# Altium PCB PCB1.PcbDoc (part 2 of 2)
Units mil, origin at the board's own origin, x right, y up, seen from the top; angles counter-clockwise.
Board outline 6184.85 x 2780 mil, 2 copper layers (Top Layer, Bottom Layer); 130 components, 145 nets, 531 pads, 99 vias.
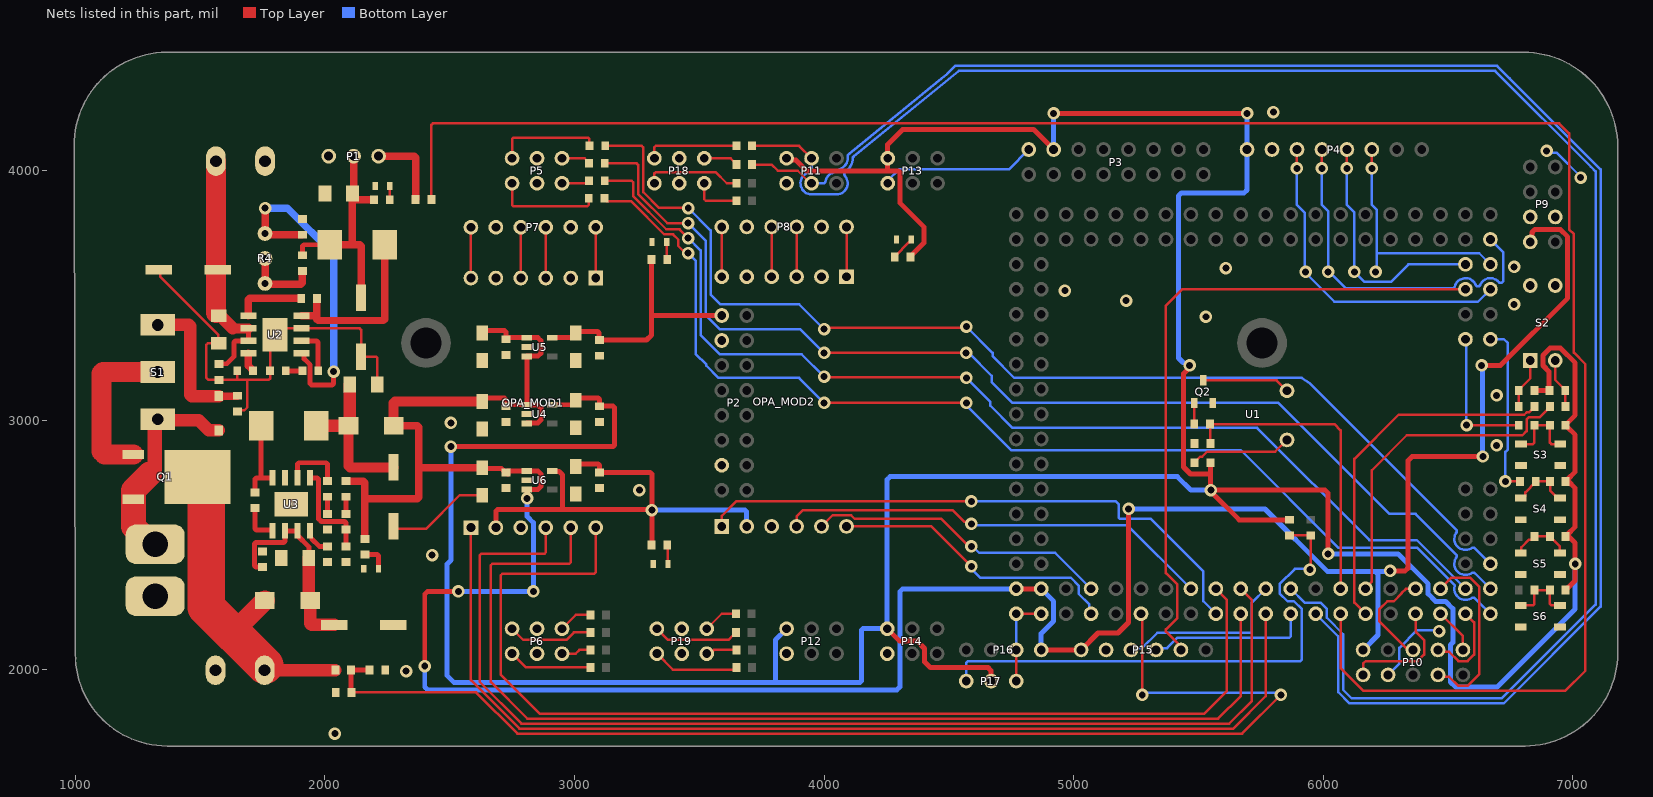
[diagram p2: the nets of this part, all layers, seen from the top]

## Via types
v1: diameter 50, hole 28, Top Layer to Bottom Layer, 99 vias

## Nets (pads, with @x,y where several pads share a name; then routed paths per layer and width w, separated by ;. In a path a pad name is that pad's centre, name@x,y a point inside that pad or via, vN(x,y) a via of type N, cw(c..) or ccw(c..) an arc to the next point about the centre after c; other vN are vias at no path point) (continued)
20.6: R42.2 U1.49 | length 555
  Top Layer w10: v1(6575,2980.91) 6782.6,2980.91 R42.2@6783.5,2980
  Bottom Layer w10: U1.49@6570,3325 6572.5,3322.5 6572.5,2983.41 v1(6575,2980.91)
20.7: R43.2 U1.50 | length 693.4
  Top Layer w10: v1(6730,2755) R43.2@6788.5,2755
  Bottom Layer w10: U1.50@6670,3325 6724.14,3325 6740,3309.14 6740,2883.43 6730,2873.43 v1(6730,2755)
20.10: P15.5 U1.53 | length 2668.7
  Top Layer w10: P15.5@5430,2080 5430,2093.27 5370,2153.27 5370,2162.03 5414.53,2206.56 5414.53,2343.44 5370,2387.97 5370,3460 5435,3525 U1.53@6570,3525
20.11: P4.3 U1.54 | length 1317.8
  Top Layer w10: v1(5895,4010) P4.3@5895,4085
  Bottom Layer w10: v1(5895,4010) 5895,3862.97 5925.47,3832.5 5925.47,3599.53 v1(5930,3595) 5930,3590 6045,3475 6620,3475 U1.54@6670,3525
20.12: P4.5 U1.55 | length 993
  Top Layer w10: v1(6095,4010) P4.5@6095,4085
  Bottom Layer w10: v1(6095,4010) 6095,3862.97 6125,3832.97 v1(6125,3595) 6165,3555 6271.17,3555 6341.17,3625 U1.55@6570,3625
20.13: P4.6 U1.56 | length 973.8
  Top Layer w10: v1(6195,4010) P4.6@6195,4085
  Bottom Layer w10: v1(6195,4010) 6195,3862.97 6215,3842.97 6215,3669.53 ; v1(6210,3595) 6215,3600 6215,3669.53 ; U1.56@6670,3625 6625.47,3669.53 6215,3669.53
20.14: P4.4 U1.57 | length 1470.9
  Top Layer w10: v1(5995,4010) P4.4@5995,4085
  Bottom Layer w10: v1(5995,4010) 5995,3862.97 6020,3837.97 v1(6020,3595) 6025,3595 6090,3530 6521.72,3530 6524.65,3532.93 6526.58,3534.86 cw(c6570,3525) 6610.83,3542.76 ccw(c6620,3546.75) 6629.15,3542.73 cw(c6670,3525) 6703.67,3554.14 6703.91,3553.9 6706.84,3550.97 6710.98,3550.97 6715.13,3550.97 6718.05,3553.9 6720.98,3556.82 6720.98,3674.02 U1.57@6670,3725
21.2: R19.1 U1.38 | length 4365.8
  Top Layer w10: R19.1@3121.5,3960 3229.14,3960 3235,3954.14 3235,3898.43 3367.68,3765.75 3394.85,3765.75 3395.6,3765 3421.06,3765 v1(3455.7,3730.35) ; v1(4000,3175) 4002.5,3172.5 4567.5,3172.5 v1(4570,3170)
  Bottom Layer w10: v1(3455.7,3730.35) 3505.47,3680.58 3505.47,3341.56 3582.5,3264.53 3910.47,3264.53 v1(4000,3175) ; v1(4570,3170) 4666.56,3073.44 4666.56,3058.44 4755.47,2969.53 5735.47,2969.53 6185,2520 6375,2520 U1.38@6570,2325
21.3: R20.2 U1.39 | length 4505.9
  Top Layer w10: R20.2@3120,3890 3120,3888.03 3130.75,3877.28 3227.86,3877.28 3359.4,3745.75 3386.57,3745.75 3387.32,3745 3395,3745 3415.7,3724.3 3415.7,3699.3 3445,3670 v1(3455,3670) ; v1(4000,3070) v1(4570,3070)
  Bottom Layer w10: v1(3455,3670) 3485,3640 3485,3266.17 3528.28,3222.89 3528.28,3218.75 3577.03,3170 3900,3170 v1(4000,3070) ; v1(4570,3070) 4570,3060 4749.53,2880.47 5669.53,2880.47 6060,2490 6376.72,2490 6526.59,2340.13 6526.59,2335.98 6526.59,2334.91 ccw(c6570,2325) 6597.56,2290.03 6600.83,2290.03 6604.97,2290.03 6624.56,2270.44 U1.39@6670,2225
21.4: R21.1 U1.40 | length 4558
  Top Layer w10: R21.1@3121.5,4030 3122.28,4029.22 3249.14,4029.22 3255,4023.36 3255,3906.72 3371.72,3790 3454.65,3790 v1(3455,3790.35) ; v1(4000,3270) v1(4569.18,3270)
  Bottom Layer w10: v1(3455,3790.35) 3525.47,3719.87 3525.47,3421.56 3582.5,3364.53 3905.47,3364.53 v1(4000,3270) ; v1(4569.18,3270) 4580,3270 4671.56,3178.44 4671.56,3153.44 4755.47,3069.53 5820.47,3069.53 6265,2625 6370,2625 6532.1,2462.9 6535.03,2459.97 6535.03,2455.83 6535.03,2452.56 ccw(c6570,2425) 6597.56,2390.03 6600.83,2390.03 6604.97,2390.03 6607.9,2387.1 U1.40@6670,2325
21.5: R22.2 U1.41 | length 4554.5
  Top Layer w10: R22.2@3122.99,4100 3268.83,4100 3275.47,4093.36 3275.47,3914.53 3339.22,3850.78 3455.38,3850.78 v1(3455.82,3850.34) ; v1(4000,3365) 4005,3370 4565,3370 v1(4570,3375)
  Bottom Layer w10: v1(3455.82,3850.34) 3545.47,3760.69 3545.47,3504.53 3585.47,3464.53 3900.47,3464.53 v1(4000,3365) ; v1(4570,3375) 4675.05,3269.95 4675.05,3256.98 4762.03,3170 5911.53,3170 5914.58,3170 5946.36,3148.64 5947.05,3147.95 6532.1,2562.9 6535.03,2559.97 6535.03,2555.83 6535.03,2552.56 ccw(c6570,2525) 6597.56,2490.03 6600.83,2490.03 6604.97,2490.03 6607.9,2487.1 U1.41@6670,2425
22.0: P10.5 U1.34 | length 409.7
  Top Layer w10: P10.5@6360,2080 6350.61,2089.39 6330.61,2089.39 6225.47,2194.53 6225.47,2243.44 6257.03,2275 6282.97,2275 6314.53,2306.56 6314.53,2307.5 6331.33,2324.3 6369.3,2324.3 U1.34@6370,2325
22.1: P10.1 U1.35 | length 182.3
  Top Layer w10: U1.35@6470,2225 6560,2135 P10.1@6560,2080
22.2: P10.4 U1.36 | length 741.9
  Top Layer w10: P10.4@6460,1980 6467.5,1972.5 6504.53,1972.5 6541.56,1935.47 6578.44,1935.47 6624.53,1981.56 6624.53,2333.44 6588.44,2369.53 6514.53,2369.53 U1.36@6470,2325
22.3: P10.3 U1.37 | length 351.5
  Top Layer w10: P10.3@6460,2080 6467.5,2072.5 6504.53,2072.5 6541.56,2035.47 6578.44,2035.47 6604.53,2061.56 6604.53,2190.47 U1.37@6570,2225
23.1: P10.10 U1.33 | length 482.4
  Top Layer w10: P10.10@6160,1980 6160,2025 6170.47,2035.47 6378.44,2035.47 6404.53,2061.56 6404.53,2119.38 6370,2153.9 U1.33@6370,2225
33.4: P15.3 U1.22 | length 709.3
  Bottom Layer w10: P15.3@5230,2080 5237.5,2087.5 5274.53,2087.5 5335,2147.97 5708.67,2147.97 5714.53,2153.83 5714.53,2269.53 U1.22@5770,2325
33.5: P15.4 U1.23 | length 653.5
  Bottom Layer w10: P15.4@5330,2080 5337.5,2087.5 5374.53,2087.5 5415,2127.97 5864.14,2127.97 5870,2133.83 U1.23@5870,2225
33.6: P11.3 R46.1 U1.24 | length 7452.1
  Top Layer w10: R46.1@3711.5,4100 3900,4100 P11.3@3950,4050
  Bottom Layer w10: P11.3@3950,4050 3950,4000.39 3948.14,3997.79 cw(c3940,4003.6) 3941.89,3993.78 ccw(c3950,3950) 3911.59,3972.53 ccw(c3950,3950) 3950,3905.47 4034.39,3905.47 ccw(c4034.39,3915.47) 4035.34,3905.52 4040.84,3906.05 cw(c4041.8,3896.09) 4043.24,3905.99 ccw(c4050,3950) 4083.96,3978.8 cw(c4091.53,3985.34) 4081.53,3985.36 ccw(c3977.43,3986.62) 4081.52,3988 cw(c4091.52,3988.11) 4085.92,3996.4 ccw(c4050,4050) 4114.51,4051.55 4114.51,4052.47 4117.79,4055.76 4117.84,4055.8 4118.5,4056.34 4539.38,4400 6688.65,4400 7072.61,4016.04 7091.62,3997.03 7091.62,2261.77 6715.33,1885.47 6114.53,1885.47 6080.47,1919.53 6080.47,2142.81 6014.53,2208.76 6014.53,2243.44 5988.44,2269.53 5925.47,2269.53 U1.24@5870,2325
33.7: P11.4 R47.2 U1.25 | length 7129.6
  Top Layer w10: R47.2@3711.5,4025 3790,4025 3815,4000 3894.6,4000 3944.6,3950 P11.4@3950,3950
  Bottom Layer w10: P11.4@3950,3950 4000.54,3950 4003.47,3952.93 4005.78,3955.24 cw(c4050,3950) 4030.87,3990.21 ccw(c4026.52,3999.21) 4031.86,3990.76 cw(c4057.95,3949.96) 4044.65,3996.53 4045.56,3997.02 4071.14,4010.81 ccw(c4050,4050) 4094.51,4051.29 4094.51,4051.55 4094.51,4060.76 4104.37,4070.62 4104.48,4070.71 4110.66,4076.11 4471.02,4370 4493.7,4388.52 4494.44,4389.19 4525.25,4420 6696.94,4420 6746.95,4369.98 7111.62,4005.32 7111.62,2253.48 6723.61,1865.47 6106.24,1865.47 6060.47,1911.24 6060.47,2134.53 U1.25@5970,2225
33.9: R8.1 U1.27 | length 8326.6
  Top Layer w10: R8.1@2426.5,3885 2426.5,4184.14 2432.35,4190 6944.93,4190 6985,4149.93 6985,3765.4 7004.53,3745.87 7004.53,3270.96 7050,3225.49 7050,1996.33 6969.14,1915.47 6161.56,1915.47 6070,2007.03 U1.27@6070,2225
33.10: R30.1 R31.1 U1.28 | length 1247.6
  Top Layer w10: R31.1@5547.84,2906.81 5546.5,2908.15 R30.1@5546.5,2985 6045,2985 6070,2960 U1.28@6070,2325
33.11: R40.2 U1.29 | length 1447.9
  Top Layer w10: U1.29@6170,2225 6125.47,2269.53 6125.47,2845.47 6302.28,3022.28 6805.82,3022.28 6816.25,3032.72 6826.18,3032.72 6846.5,3053.03 R40.2@6846.5,3055
33.12: R41.2 U1.30 | length 1332.8
  Top Layer w10: U1.30@6170,2325 6170,2329.69 6195,2354.69 6195,2800 6335,2940 6798.18,2940 6815,2956.82 6815,3003.18 6824.53,3012.72 6868.19,3012.72 6908.5,3053.03 R41.2@6908.5,3055
A0: OPA_MOD1.7 U1.21 | length 4260.1
  Top Layer w10: OPA_MOD1.7@2585,2570 2585,1959.14 2779.14,1765 5640,1765 5770,1895 U1.21@5770,2225
A1: OPA_MOD1.10 U1.20 | length 4544.8
  Top Layer w10: OPA_MOD1.10@2885,2570 2885,2470.86 2879.14,2465 2625.86,2465 2620,2459.14 2620,1952.43 2787.43,1785 5623.67,1785 5714.53,1875.86 5714.53,2280.47 U1.20@5670,2325
A2: OPA_MOD1.11 U1.19 | length 4364.5
  Top Layer w10: OPA_MOD1.11@2985,2570 2985,2430.86 2979.14,2425 2670.86,2425 2665,2419.14 2665,1950.86 2810.86,1805 5579.14,1805 5670,1895.86 U1.19@5670,2225
A3: OPA_MOD1.12 U1.18 | length 4401.4
  Top Layer w10: OPA_MOD1.12@3085,2570 3085,2390.86 3079.14,2385 2711.33,2385 2705.47,2379.14 2705.47,1979.53 2860,1825 5523.67,1825 5614.53,1915.86 5614.53,2280.47 U1.18@5570,2325
A4: OPA_MOD2.7 U1.17 | length 2334.1
  Top Layer w10: OPA_MOD2.7@3590,2575 3590,2617.22 3647.78,2675 v1(4590,2675)
  Bottom Layer w10: v1(4590,2675) 5169.14,2675 5180,2664.14 5180,2610.86 5185.91,2604.95 5310.05,2604.95 5520,2395 5520,2275 U1.17@5570,2225
A5: OPA_MOD2.10 U1.16 | length 1760.8
  Top Layer w10: OPA_MOD2.10@3890,2575 3890,2615 3915,2640 4515,2640 4562.35,2592.65 4582.35,2592.65 v1(4590,2585)
  Bottom Layer w10: v1(4590,2585) 4594.53,2580.47 5214.53,2580.47 U1.16@5470,2325
A11: C27.1 R27.2 R28.1 U1.11 | length 4906.3
  Top Layer w10: R28.1@2106.5,1910 2605.86,1910 2770.86,1745 5675,1745 v1(5830,1900) ; U1.11@5270,2225 5274.53,2220.47 5274.53,1900.47 v1(5275,1900)
  Top Layer w20: R28.1@2105,1911.5 R27.2@2105,2000 C27.1@2178.5,2000
  Bottom Layer w10: v1(5275,1900) 5282.5,1907.5 5822.5,1907.5 v1(5830,1900)
A16: OPA_MOD2.11 U1.8 | length 1220.4
  Top Layer w10: OPA_MOD2.11@3990,2575 4034.53,2619.53 4108.44,2619.53 4122.97,2605 4470,2605 4580,2495 v1(4590,2495)
  Bottom Layer w10: v1(4590,2495) 4595.62,2495 4621.1,2469.53 4925.47,2469.53 U1.8@5070,2325
A17: OPA_MOD2.12 U1.7 | length 1167.7
  Top Layer w10: OPA_MOD2.12@4090,2575 4430,2575 v1(4590,2415)
  Bottom Layer w10: v1(4590,2415) 4590,2405 4625,2370 4985,2370 4985.47,2369.53 4988.44,2369.53 5020,2337.97 5020,2305 5063.51,2261.49 5063.51,2231.49 U1.7@5070,2225
GND: C1.2 C2.1 C3.1 C5.2 C6.2 C7.1 C8.2 C9.1 C10.2 C12.1 C13.2 C14.1 C15.2 C16.1 C17.2 C18.1 C19.2 C20.1 C21.2 C22.1 C23.2 C24.1 C25.2 C26.1 C27.2 DCIN.2 DCOUT1.2 DCOUT2.2 LED3V3.C LED5V.C LEDCAM.C LEDOP.C LEDSteer.C OPA_MOD1.2 OPA_MOD1.5 OPA_MOD1.9 OPA_MOD2.2 OPA_MOD2.5 OPA_MOD2.9 P1.3 P2.4 P2.14 P3.2 P4.2 P5.3 P5.4 P6.3 P6.4 P7.2 P7.5 P8.2 P8.5 P9.5 P9.6 P10.8 P11.6 P12.6 P13.6 P14.6 P15.2 P16.2 P17.1 P18.3 P18.4 P19.3 P19.4 Q2.2 R1.1 R2.1 R5.2 R9.1 R12.1 R28.2 R31.2 S2.3 S2.4 S3.1 S4.1 S5.1 S6.1 U1.1 U1.3 U2.0 U2.7 U3.0 U3.7 U4.2 U5.2 U6.2 | length 3769.1
  Top Layer w10: C1.2@1333.78,3603.5 1340.76,3596.52 1340.76,3574.68 1572.2,3343.24 1572.2,3311.3 C2.1@1575,3308.5 1530.86,3308.5 1525,3302.65 1525,3170 1532.99,3162.01 C3.1@1575,3162.01 ; C3.1@1575.36,3161.65 1648.5,3161.65 ; R2.1@1648.5,3198.5 1648.5,3161.65 ; R1.1@1650,3035.51 1654.57,3040.08 1676.86,3040.08 1689.14,3052.36 1689.14,3161.65 ; C12.1@2210.12,3143.5 2210.12,3249.54 2204.26,3255.39 C6.2@2145,3255.39 2145,3362.65 2139.14,3368.5 1825,3368.5 U2.0@1800,3343.5 1780,3323.5 1780,3167.5 1774.14,3161.65 1689.14,3161.65 ; C13.2@2275,2575.39 2285.39,2565 2405,2565 2539.88,2699.88 C23.2@2630,2699.88 ; P17.1@4770,1955 P16.2@4770,2080 ; U1.1@4770,2225 U1.3@4870,2225 ; 1648.5,3161.65 1689.14,3161.65
  Bottom Layer w10: P13.6@4255,3950 4255,3960 4300.47,4005.47 4740.47,4005.47 P3.2@4820,4085 ; P16.2@4770,2080 U1.1@4770,2225 ; P10.8@6260,1980 6305.47,2025.47 6305.47,2088.44 6376.28,2159.25 6460.75,2159.25 v1(6465,2155) ; v1(6895,4080) 6902.03,4072.97 6935,4072.97 7030,3977.97 7030,3973.8 v1(7031.62,3972.18)
  other v1: 2040,1745 2325,1995 2430,2460 3260,2720 6695,2900 2505,2990 6695,3100 5530,3415 6765,3465 5210,3480 4965,3520 5610,3610 6765,3615 5800,4235
NetB1_1: B1.1 R29.2 | length 409.1
  Top Layer w10: R29.2@5485,2830 5485,2831.97 5507.12,2854.09 5515.09,2854.09 5535.09,2874.09 5807.52,2874.09 B1.1@5855,2921.57
NetB1_2: B1.2 Q2.3 | length 352.3
  Top Layer w10: Q2.3@5520,3160.28 5813.15,3160.28 B1.2@5855,3118.43
NetC4_1: C4.1 U2.1 | length 277.9
  Top Layer w30: U2.1@1693.7,3418.5 1693.7,3482.65 1699.56,3488.5 C4.1@1905,3488.5
NetC4_2: C4.2 L2.1 U2.8 | length 719.7
  Top Layer w10: 1966.5,3418.5 1967.99,3420
  Top Layer w30: U2.8@1906.3,3418.5 1966.5,3418.5 ; C4.2@1967.99,3488.5 1967.99,3420 1967.99,3405.86 1973.85,3400 2234.38,3400 2240.24,3405.86 L2.1@2240.24,3703.5
NetC7_2: C7.2 R7.1 | length 67
  Top Layer w20: C7.2@1842.99,3198.5 R7.1@1910,3198.5
NetC8_1: C8.1 C9.2 C10.1 D2.K U3.2 U3.3 | length 831.4
  Top Layer w10: U3.3@1890,2538.5 U3.3@1890,2557.2
  Top Layer w20: C10.1@1750,2412.01 1723.14,2412.01 1717.28,2417.87 1717.28,2504.85 1723.14,2510.71 1834.14,2510.71 1840,2516.57 U3.2@1840,2557.2 U3.3@1890,2557.2 ; U3.3@1890,2538.5 1935.24,2493.27 C9.2@1935.24,2448.5
  Top Layer w50: C9.2@1935.24,2448.5 1935.24,2283.82 D2.K@1940.55,2278.5 1940.55,2185.86 1946.41,2180 C8.1@2036.89,2180
NetC11_1: C11.1 U3.1 | length 156.2
  Top Layer w10: U3.1@1787.2,2560 U3.1@1790,2557.2
  Top Layer w20: C11.1@1720,2648.5 1720,2565.86 1725.86,2560 U3.1@1787.2,2560
NetC11_2: C11.2 L1.1 U3.8 | length 333.6
  Top Layer w20: C11.2@1720,2711.5 1720,2763.95 1725.86,2769.8 1744.76,2769.8 ; L1.1@1744.76,2978.5 1744.76,2769.8 ; U3.8@1790,2769.8 1744.76,2769.8
NetC12_2: C12.2 C13.1 D3.A L1.2 | length 640.5
  Top Layer w10: D3.A@2094.45,2978.5 D3.A@2099.88,2983.94
  Top Layer w40: D3.A@2094.45,2978.5 2094.45,2817.47 2100.31,2811.61 C13.1@2275,2811.61
  Top Layer w50: L1.2@1965.24,2978.5 D3.A@2094.45,2978.5 ; D3.A@2099.88,2983.94 C12.2@2099.88,3143.5
NetC14_2: C14.2 R14.1 | length 68.5
  Top Layer w20: C14.2@2010,2625 R14.1@2010,2693.5
NetD1_A: D1.A R1.2 S1.3 | length 598.7
  Top Layer w10: R1.2@1648.9,3097.4 R1.2@1650,3098.5
  Top Layer w30: D1.A@1575,3097.4 R1.2@1648.9,3097.4
  Top Layer w50: S1.3@1330,3382.48 1454.14,3382.48 1460,3376.62 1460,3103.26 1465.86,3097.4 D1.A@1575,3097.4
NetD1_K: D1.K DCIN.1 Q1.3 S1.1 | length 851.4
  Top Layer w10: DCIN.1@1303.25,2503.5 DCIN.1@1320,2503.5 ; S1.1@1330,3004.53 S1.1@1334.53,3000
  Top Layer w50: S1.1@1334.53,3000 1495,3000 1535.39,2959.61 D1.K@1575,2959.61
  Top Layer w60: 1298.11,2784.57 1318.11,2804.57 1318.11,2992.64 S1.1@1330,3004.53
  Top Layer w100: 1298.11,2784.57 1232.13,2718.58 1232.13,2574.63 DCIN.1@1303.25,2503.5
NetLED3V3_A: LED3V3.A R16.2 | length 99.1
  Top Layer w10: R16.2@4283.5,3655 4283.5,3656.97 4340.79,3714.25 4343.7,3714.25 4349.53,3720.08 LED3V3.A@4349.53,3725
NetLED5V_A: LED5V.A R13.1 | length 108.1
  Top Layer w20: R13.1@2160,2462.01 2208.67,2462.01 2214.53,2456.15 LED5V.A@2214.53,2405
NetLEDCAM_A: LEDCAM.A R17.2 | length 70.8
  Top Layer w10: LEDCAM.A@3369.53,3715 3369.53,3646.97 R17.2@3371.5,3645
NetLEDOP_A: LEDOP.A R18.2 | length 76.3
  Top Layer w10: R18.2@3371.5,2500 3374.53,2496.97 LEDOP.A@3374.53,2425
NetLEDSteer_A: LEDSteer.A R6.1 | length 55
  Top Layer w10: R6.1@2260,3883.5 LEDSteer.A@2260,3938.5
NetOPA_MOD1_1: OPA_MOD1.1 P7.6 | length 203.5
  Top Layer w10: OPA_MOD1.1@3085,3570 P7.6@3085,3773.5
NetOPA_MOD1_3: OPA_MOD1.3 P7.4 | length 203.5
  Top Layer w10: OPA_MOD1.3@2885,3570 P7.4@2885,3773.5
NetOPA_MOD1_4: OPA_MOD1.4 P7.3 | length 203.5
  Top Layer w10: OPA_MOD1.4@2785,3570 P7.3@2785,3773.5
NetOPA_MOD1_6: OPA_MOD1.6 P7.1 | length 203.5
  Top Layer w10: OPA_MOD1.6@2585,3570 P7.1@2585,3773.5
NetOPA_MOD2_1: OPA_MOD2.1 P8.6 | length 200
  Top Layer w10: OPA_MOD2.1@4090,3575 P8.6@4090,3775
NetOPA_MOD2_3: OPA_MOD2.3 P8.4 | length 200
  Top Layer w10: OPA_MOD2.3@3890,3575 P8.4@3890,3775
NetOPA_MOD2_4: OPA_MOD2.4 P8.3 | length 200
  Top Layer w10: OPA_MOD2.4@3790,3575 P8.3@3790,3775
NetOPA_MOD2_6: OPA_MOD2.6 P8.1 | length 200
  Top Layer w10: OPA_MOD2.6@3590,3575 P8.1@3590,3775
NetP1_1: P1.1 R8.2 | length 318.6
  Top Layer w30: P1.1@2215,4058.5 2357.65,4058.5 2363.5,4052.65 R8.2@2363.5,3885
NetP5_1: P5.1 R21.2 | length 117.9
  Top Layer w10: P5.1@2950,4050 3040.47,4050 3058.5,4031.97 R21.2@3058.5,4030
NetP5_2: P5.2 R19.2 | length 112.6
  Top Layer w10: P5.2@2950,3950 3048.5,3950 R19.2@3058.5,3960
NetP5_5: P5.5 R22.1 | length 418.6
  Top Layer w10: P5.5@2750,4050 2750,4126.86 2755.86,4132.72 3054.14,4132.72 3060,4126.86 R22.1@3060,4100
NetP5_6: P5.6 R20.1 | length 425.6
  Top Layer w10: P5.6@2750,3950 2750,3863.14 2755.86,3857.28 3051.15,3857.28 3057.01,3863.14 R20.1@3057.01,3890
NetP6_1: P6.1 R25.2 | length 136.3
  Top Layer w10: P6.1@2950,2165 3005,2220 R25.2@3063.5,2220
NetP6_2: P6.2 R23.2 | length 119.7
  Top Layer w10: P6.2@2950,2065 3005,2065 3020,2080 R23.2@3063.5,2080
NetP6_5: P6.5 R26.1 | length 344.2
  Top Layer w10: P6.5@2750,2165 2794.53,2120.47 2968.44,2120.47 2997.97,2150 R26.1@3063.5,2150
NetP6_6: P6.6 R24.1 | length 336.3
  Top Layer w10: P6.6@2750,2065 2805,2010 R24.1@3063.5,2010
NetP17_3: P17.3 R32.1 R33.2 | length 2149.7
  Top Layer w10: R32.1@5865,2538.5 R33.2@5950,2538.5 5950,2405 v1(5946.46,2401.46)
  Bottom Layer w10: P17.3@4570,1955 4570,2029.14 4575.86,2035 5908.67,2035 5914.53,2040.86 5914.53,2243.44 5882.97,2275 5857.03,2275 5825.47,2306.56 5825.47,2343.44 5887.03,2405 5942.93,2405 v1(5946.46,2401.46)
NetP18_1: P18.1 R48.2 | length 388.7
  Top Layer w10: P18.1@3320,3950 3320,3989.14 3325.86,3995 3565,3995 3610,3950 R48.2@3648.5,3950
NetP18_2: P18.2 R46.2 | length 375.1
  Top Layer w10: P18.2@3320,4050 3320,4094.14 3325.86,4100 R46.2@3648.5,4100
NetP18_5: P18.5 R49.1 | length 195.1
  Top Layer w10: P18.5@3520,3950 3520,3885.86 3525.86,3880 R49.1@3648.5,3880
NetP18_6: P18.6 R47.1 | length 140
  Top Layer w10: P18.6@3520,4050 3625.47,4050 3648.5,4026.97 R47.1@3648.5,4025
NetP19_1: P19.1 R52.2 | length 349.2
  Top Layer w10: P19.1@3330,2065 3394.53,2000.47 3638.98,2000.47 R52.2@3648.5,2010
NetP19_2: P19.2 R50.2 | length 348.8
  Top Layer w10: P19.2@3330,2165 3374.53,2120.47 3617.48,2120.47 3634.29,2137.28 3636.26,2137.28 3647.01,2148.03 R50.2@3647.01,2150
NetP19_5: P19.5 R53.1 | length 124.7
  Top Layer w10: P19.5@3530,2065 3543.27,2065 3558.27,2080 R53.1@3648.5,2080
NetP19_6: P19.6 R51.1 | length 141.9
  Top Layer w10: P19.6@3530,2165 3590,2225 R51.1@3647.01,2225
NetQ1_2: Q1.2 S1.2 | length 672.1
  Top Layer w80: Q1.2@1232.13,2863.27 1116.73,2863.27 1105,2875 1105,3187.65 1110.86,3193.5 S1.2@1330,3193.5
NetQ2_1: Q2.1 R30.2 | length 85.1
  Top Layer w10: Q2.1@5482.6,3069.72 5482.6,2985.91 R30.2@5483.5,2985
NetR2_2: R2.2 U2.4 | length 77.4
  Top Layer w10: R2.2@1711.5,3198.5 R2.2@1711.5,3200.47
  Top Layer w30: U2.4@1693.7,3268.5 1693.7,3218.27 R2.2@1711.5,3200.47
NetR3_1: R3.1 R4.2 R4.ADJ | length 301.5
  Top Layer w10: R4.2@1760,3548.5 R4.2@1763.5,3545 ; 1904.14,3545 1910,3550.86
  Top Layer w30: R4.2@1760,3548.5 R4.ADJ@1760,3648.5 ; R4.2@1763.5,3545 1904.14,3545 ; 1910,3550.86 R3.1@1910,3598.5
NetR4_1: R4.1 R5.1 U2.5 | length 1359.4
  Top Layer w10: U2.5@1906.3,3268.5 1908.82,3268.5 U2.5@1916.62,3260.71
  Top Layer w20: U2.5@1916.62,3260.71 1916.62,3246.57 1940.75,3222.43 1940.75,3147.07 1946.61,3141.21 2029.14,3141.21 2035,3147.07 v1(2035,3195)
  Top Layer w30: v1(1760,3850) R4.1@1760,3748.5 1765,3743.5 R5.1@1910,3743.5
  Bottom Layer w30: v1(1760,3850) 1850,3850 2035,3665 v1(2035,3195)
NetR7_2: R7.2 U2.6 | length 183.3
  Top Layer w20: U2.6@1906.3,3318.5 1967.13,3318.5 1972.99,3312.65 R7.2@1972.99,3198.5
NetR9_2: R9.2 U3.4 | length 110.4
  Top Layer w10: U3.4@1940,2557.2 1947.8,2549.41 1947.8,2524.49
  Top Layer w20: 1947.8,2524.49 1977.28,2495 R9.2@2010,2495
NetR10_1: R10.1 R11.2 | length 68.5
  Top Layer w20: R11.2@2085,2625 R10.1@2085,2693.5
NetR11_1: R11.1 R12.2 U3.5 | length 406.5
  Top Layer w20: U3.5@1940,2769.8 1969.14,2769.8 1975,2763.95 1975,2605.32 1986.07,2594.25 2079.14,2594.25 2085,2588.39 R12.2@2085,2495
NetR14_2: R14.2 U3.6 | length 246.8
  Top Layer w20: U3.6@1890,2769.8 1890,2824.14 1895.86,2830 2004.14,2830 2010,2824.14 R14.2@2010,2756.5
NetR34_2: R34.2 R40.1 S2.1 | length 204.3
  Top Layer w10: R40.1@6783.5,3055 R34.2@6783.5,3120 6783.5,3121.97 6830,3168.46 S2.1@6830,3240
NetR35_2: R35.2 R41.1 S2.2 | length 202.2
  Top Layer w10: S2.2@6930,3240 6930,3161.97 6970,3121.97 R35.2@6970,3120 6970,3056.5 R41.1@6971.5,3055
NetR36_2: R36.2 R42.1 S3.2 | length 300.6
  Top Layer w10: S3.2@6792.52,2905 6840.64,2905 6846.5,2910.86 R42.1@6846.5,2980 R36.2@6908.5,2980 6908.5,2910.86 6914.36,2905 S3.2@6950,2905
NetR37_2: R37.2 R43.1 S4.2 | length 243.5
  Top Layer w10: S4.2@6791.26,2688.31 6801.1,2688.31 6809.88,2697.09 6809.88,2711.42 6851.5,2753.03 R43.1@6851.5,2755 R37.2@6908.5,2755 6908.91,2754.6 6908.91,2718.3 6938.9,2688.31 S4.2@6948.74,2688.31
NetR38_2: R38.2 R44.1 S5.2 | length 242
  Top Layer w10: S5.2@6791.26,2468.31 6794.41,2471.46 6794.41,2491.23 6825.47,2522.28 6835.75,2522.28 6846.5,2533.03 R44.1@6846.5,2535 R38.2@6908.5,2535 6908.5,2533.03 6919.25,2522.28 6921.04,2522.28 6948.74,2494.58 S5.2@6948.74,2468.31
NetR39_2: R39.2 R45.1 S6.2 | length 274
  Top Layer w10: S6.2@6791.26,2258.31 6840.64,2258.31 6846.5,2264.16 R45.1@6846.5,2320 R39.2@6908.5,2320 6908.5,2264.16 6914.36,2258.31 S6.2@6948.74,2258.31
VCC3V3: C17.1 C18.2 P3.4 P4.1 P11.5 P12.5 P13.5 P14.5 P17.2 R16.1 R29.1 R32.2 R34.1 R35.1 R36.1 R37.1 R38.1 R39.1 U4.5 | length 15483.7
  Top Layer w10: P11.5@3850,4050 P11.5@3857.5,4042.5 ; R16.1@4346.5,3655 R16.1@4346.5,3656.97 ; v1@5465,3209.18 v1(5465,3220) ; R35.1@6907.01,3118.03 R35.1@6907.01,3120
  Top Layer w20: v1(2505,2895) 3154.14,2895 3160,2900.86 3160,3050.64 3154.14,3056.5 C18.2@3100,3056.5 3100,3084.14 3094.14,3090 3014.88,3090 C17.1@3005,3080.12 2987.28,3062.4 U4.5@2911.18,3062.4 ; P11.5@3857.53,4042.53 3881.22,4042.53 ; 3881.24,4042.5 3887.46,4042.5 3929.49,4000.47 ; 3929.53,4000.47 3930,4000 4255,4000 ; P14.5@4253.03,2165 4303.03,2115 4373.07,2115 4402.56,2085.51 4402.56,2032.44 4425.66,2009.34 4656.72,2009.34 4668.44,1997.62 4668.44,1956.56 P17.2@4670,1955 ; R16.1@4346.5,3656.97 4400,3710.47 4400,3775 4305,3870 4305,3994.14 4299.14,4000 4255,4000 ; P3.4@4920,4085 4840,4165 4315,4165 4255,4105 P13.5@4255,4050 4255,4000 ; v1(4920,4230) v1(5695,4230) ; v1@5465,3209.18 5462.29,3209.18 5440,3186.88 5440,2813.25 5468.25,2785 5547.99,2785 ; v1@5547.99,2717.01 5663.5,2601.5 R32.2@5865,2601.5 ; v1@5547.99,2720 5547.99,2785 ; R29.1@5547.99,2830 5547.99,2785 ; v1(5550,2720) 6008.28,2720 6020,2708.28 v1(6020,2465) ; R34.1@6846.5,3120 R35.1@6905.04,3120 ; R35.1@6907.01,3118.03 R35.1@6905.04,3120 ; R35.1@6907.01,3120 R35.1@6905.04,3120 ; R39.1@6971.5,2320 6971.5,2321.97 6977.24,2327.72 6979.21,2327.72 7010,2358.5 v1(7010,2425) 7010,2508.3 6991.02,2527.28 6990.93,2527.28 6979.21,2539 6979.21,2542.72 7010,2573.5 7010,2728.3 6983.3,2755 R37.1@6971.5,2755 ; R37.1@6971.5,2756.97 6977.24,2762.72 6979.21,2762.72 7010,2793.5 7010,2903.61 7009.38,2904.24 7009.38,2942.12 6979.21,2972.28 6977.24,2972.28 6971.5,2978.03 R36.1@6971.5,2980 6971.5,2981.97 7010,3020.47 7010,3230.04 6950.51,3289.53 6909.49,3289.53 6880.47,3260.51 6880.47,3219.49 6905,3194.96 6905,3120.04 R35.1@6905.04,3120
  Bottom Layer w20: v1(2505,2895) 2505,2439.3 2490,2424.3 2490,1976.72 2516.72,1950 3805,1950 ; P12.5@3850,2165 3805,2120 3805,1950 ; P3.4@4920,4085 v1(4920,4230) ; 5438.61,3231.39 5420.47,3249.53 5420.47,3899.51 5432.19,3911.22 5683.28,3911.22 5695,3922.94 P4.1@5695,4085 v1(5695,4230) ; v1(5550,2720) 5470,2720 5415.47,2774.53 4264.75,2774.53 4253.03,2762.81 P14.5@4253.03,2165 4155.86,2165 4150,2159.14 4150,1955.86 4144.14,1950 3805,1950 ; v1(6020,2465) 6300.04,2465 6420.47,2344.57 6420.47,2304.49 6449.96,2275 6490.04,2275 6519.53,2245.51 6519.53,2109.57 6510.47,2100.51 6510.47,1951.24 6531.24,1930.47 6696.69,1930.47 7010,2243.79 v1(7010,2425)
VCC5V: C15.1 C16.2 C19.1 C20.2 C23.1 C24.2 D3.K P9.7 P10.9 P15.1 P16.1 R10.2 R13.2 U1.2 U1.4 U4.1 U4.3 U5.1 U5.3 U6.1 U6.3 | length 11787
  Top Layer w10: 2375,2805 2380.12,2810.12 ; C23.1@2630,2810.12 C23.1@2644.88,2825 ; C15.1@2630,3075.12 C15.1@2644.88,3090 ; v1@5220,2644.71 v1(5220.24,2644.95)
  Top Layer w20: v1(2400,2015) 2400,2303.28 2411.72,2315 v1(2535,2315) ; C23.1@2630,2810.12 2632.71,2807.41 2707.12,2807.41 2717.28,2797.24 2719.25,2797.24 2730.75,2785.75 C24.2@2732.72,2785.75 ; C19.1@2630,3350 2640,3360 2719.14,3360 2725,3354.14 C20.2@2725,3325 2730.91,3330.91 2853.28,3330.91 2865,3319.19 2865,3268.59 2853.28,3256.88 U5.3@2809.6,3256.88 ; C15.1@2644.88,3090 2719.14,3090 2725,3084.14 C16.2@2725,3056.5 2730.91,3062.4 U4.1@2808.82,3062.4 ; C24.2@2725,2791.5 2730.75,2797.24 2744.27,2797.24 2744.43,2797.4 2853.28,2797.4 2865,2785.69 2865,2734.31 2853.28,2722.6 U6.3@2808.82,2722.6 2809.41,2722.01 2809.41,2687.57 v1(2810,2686.98) ; U4.3@2808.82,2987.6 2810.63,2989.41 2853.28,2989.41 2865,3001.13 2865,3048.87 2853.28,3060.59 2810.63,3060.59 U4.1@2808.82,3062.4 ; U5.3@2808.82,3256.1 U4.1@2808.82,3062.4 ; U1.2@4770,2325 U1.4@4870,2325 ; P16.1@4870,2080 P15.1@5030,2080 5097.97,2147.97 5177.97,2147.97 5220,2190 v1@5220,2644.71 ; v1(6268.14,2396.74) 6328.28,2396.74 6340,2408.46 6340,2838.28 6356.72,2855 v1(6640,2855) ; v1(6635,3220) 6710,3220 6979.53,3489.53 6979.53,3735.51 6950.52,3764.53 6848.09,3764.53 6836.37,3752.81 6836.37,3721.37 P9.7@6830,3715
  Top Layer w30: R10.2@2085,2756.5 2154.14,2756.5 2160,2750.64 2160,2685 ; R13.2@2160,2525 2160,2685 ; D3.K@2275.55,2978.5 2369.14,2978.5 2375,2972.65 2375,2805 2375,2690.86 2369.14,2685 2160,2685 ; 2380.12,2810.12 C23.1@2630,2810.12
  Top Layer w40: D3.K@2275.55,2978.5 2275.55,3069.26 2281.41,3075.12 C15.1@2630,3075.12
  Bottom Layer w20: v1(2400,2015) 2400,1931.72 2411.72,1920 4291.79,1920 4303.5,1931.72 4303.5,2313.28 4315.22,2325 U1.2@4770,2325 ; v1(2535,2315) v1(2835,2315) 2835,2590.04 2810,2615.04 v1(2810,2686.98) ; P16.1@4870,2080 4870,2146.1 4920,2196.1 4920,2275 U1.4@4870,2325 ; v1(5220.24,2644.95) 5766.62,2644.95 6016.57,2395 6207.21,2395 ; P10.9@6160,2080 6219.53,2139.53 6219.53,2382.68 6207.21,2395 ; v1(6268.14,2396.74) 6266.4,2395 6207.21,2395 ; v1(6635,3220) 6637.5,3217.5 6637.5,2857.5 v1(6640,2855)
VCCBAT: C1.1 C2.2 C3.2 D2.A DCOUT1.1 DCOUT2.1 Q1.1 R27.1 U2.2 U2.3 | length 2560.7
  Top Layer w10: Q1.1@1490,2773.5 Q1.1@1525,2738.5 ; C3.2@1575,3225 C3.2@1576.66,3226.66 ; C2.2@1575,3418.74 C2.2@1580.91,3418.74 ; DCOUT2.1@1758.43,1998.5 DCOUT2.1@1758.43,2018.19 ; R27.1@2040.51,1998.5 R27.1@2042.01,2000
  Top Layer w20: C3.2@1576.66,3226.66 1606.66,3226.66 1635,3255 1635,3312.65 1640.86,3318.5 U2.3@1693.7,3318.5 U2.2@1693.7,3368.5
  Top Layer w40: 1631.14,3368.5 U2.2@1693.7,3368.5
  Top Layer w50: C2.2@1580.91,3418.74 1631.14,3368.5 ; DCOUT2.1@1758.43,1998.5 R27.1@2040.51,1998.5
  Top Layer w70: C1.1@1563.15,3596.65 C1.1@1570,3603.5 C1.1@1563.15,3610.35
  Top Layer w80: C2.2@1563.15,3430.59 C1.1@1563.15,3596.65 ; C1.1@1563.15,3610.35 DCOUT1.1@1563.15,4038.5 ; DCOUT2.1@1758.43,1998.5 1618.94,2137.99 D2.A@1759.45,2278.5
  Top Layer w150: Q1.1@1525,2738.5 1525,2251.61 DCOUT2.1@1758.43,2018.19
VCCCAM: C21.1 C22.2 P2.16 R17.1 U5.5 | length 1027.5
  Top Layer w20: U5.5@2911.18,3330.91 2986.38,3330.91 C21.1@3002.34,3346.87 ; C21.1@3005,3350.12 3011.28,3356.4 3092.98,3356.4 3098.83,3350.54 C22.2@3098.83,3321.5 ; C22.2@3100,3321.5 3288.5,3321.5 3308.5,3341.5 3308.5,3420 ; R17.1@3308.5,3645 3308.5,3420 ; P2.16@3590,3420 3308.5,3420
VCCOP: C25.1 C26.2 OPA_MOD1.8 OPA_MOD2.8 R18.1 U6.5 | length 1952.4
  Top Layer w10: C25.1@3005,2815.12 C25.1@3014.88,2825 ; v1@3308.02,2641.98 v1(3310,2640) ; R18.1@3308.5,2500 R18.1@3310,2501.5
  Top Layer w20: OPA_MOD1.8@2685,2570 2685,2636.12 2690.86,2641.98 2952.83,2641.98 ; U6.5@2911.18,2797.4 2912.99,2795.59 2938.28,2795.59 2952.83,2781.04 2952.83,2641.98 ; C25.1@3014.88,2825 3094.14,2825 3100,2819.14 C26.2@3100,2791.5 ; C26.2@3098.03,2791.5 3302.65,2791.5 3310,2784.14 v1(3310,2640) R18.1@3310,2501.5 ; v1@3308.02,2641.98 2952.83,2641.98
  Bottom Layer w20: v1(3310,2640) 3684.14,2640 3690,2634.14 OPA_MOD2.8@3690,2575
VCCSreer: C5.1 C6.1 L2.2 P1.2 R3.2 R6.2 | length 934.6
  Top Layer w10: C5.1@2110,3908.5 C5.1@2115,3913.5
  Top Layer w20: R3.2@1910,3661.5 1910,3697.65 1915.86,3703.5 L2.2@2019.76,3703.5
  Top Layer w30: L2.2@2019.76,3703.5 2110,3703.5 ; C5.1@2110,3892.01 2110,3703.5 ; C5.1@2110,3908.5 2110,3883.5 R6.2@2197.01,3883.5 ; C5.1@2115,3913.5 P1.2@2115,4058.5 ; C6.1@2145,3491.61 2145,3697.65 2139.14,3703.5 2110,3703.5
pads on no net: Designator6.1 Designator8.1 P2.10 P4.7 P4.8 P9.2 P10.2 P10.7 P11.1 P11.2 P12.1 P12.2 P13.1 P13.2 P14.1 P14.2 P15.6 U1.5 U1.6 U1.9 U1.10 U1.12 U1.13 U1.14 U1.15 U1.26 U1.31 U1.32 U1.42 U1.43 U1.45 U1.47 U1.48 U1.51 U1.52 U1.67 U1.68 U1.69 U1.70 U1.71 U1.72 U1.73 U1.109 U1.110 U1.111 U1.112 U1.113 U1.114 U1.115 U1.116 U1.117 U1.118 U1.119 U1.120 U1.121 U1.122 U4.4 U5.4 U6.4
copper on no net: | length 7.2
  Top Layer w10: 3063.5,2220 3063.5,2227.16

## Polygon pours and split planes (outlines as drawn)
GND on Top Layer "GND_L01_P000" (solid, remove dead copper, pour order 0): 2495,4559.98 2495,1535.02 595.01,1535.02 595.01,4559.98
GND on Top Layer "NONET_L-01_P-001" (solid, remove dead copper, pour order 2): 2515.55,4559.98 7389.98,4559.98 7389.98,1535.02 2509.48,1535.02
GND on Bottom Layer "GND_L02_P007" (solid, remove dead copper, pour order 7): 595.01,2062.41 cw(c1123.26,2063.27) 595.01,2064.13 cw(c1002.2,2063.47) 595.01,2064.15 595.01,2062.41 ccw(c1123.27,2063.27) 1122.4,1535.02 6856.51,1535.02 ccw(c6851.48,2073.52) 7389.98,2068.5 7389.98,4030.49 ccw(c6860.49,4030.49) 6860.49,4559.98 1122.39,4559.98 ccw(c1122.46,4032.54) 595.01,4032.54 ccw(c1122.46,4032.54) 595.01,4032.46

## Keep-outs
Keep-Out Layer:
  lines w10: 1000.73,2062.55 ccw(c1368.02,2062.55) 1368.02,1695.26 ; 1000.73,2062.65 995.88,4100.3 cw(c1368.22,4102.8) 1365.72,4475.14 6803.44,4475.26 cw(c6803.44,4097.97) 7180.73,4097.97 7180.73,2067.58 cw(c6808.4,2067.58) 6808.4,1695.26 ; 1370.73,1695.26 6810.73,1695.26

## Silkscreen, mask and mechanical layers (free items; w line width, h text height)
Top Overlay:
  text "无线串口" at 6775,4195.22 h60
  text "有刷电机接口1" at 2707.71,4183.6 h60
  text "无刷电机接口1" at 3260,4180.66 h60
  text "陀螺仪接口" at 5870.06,4165.44 h60
  text "屏幕接口" at 5065,4145 h60
  text "-" at 5773.78,4142.46 h60
  text "舵机接口" at 2005.06,4130.66 h60
  text "编码器接口1" at 3885,4130.44 h60
  text "编码器接口3" at 4294.16,4126.71 h60
  text "-" at 4798.78,4127.46 h60
  text "-" at 3928.78,4117.46 h60
  text "-" at 2828.78,4112.46 h60
  text "-" at 3398.78,4102.46 h60
  text "+" at 1405,4005 h60
  text "-" at 1880,4000.01 h60
  text "-" at 1993.78,3947.46 h60
  text "-" at 2828.78,3847.46 h60
  text "-" at 3398.78,3847.46 h60
  text "-" at 3928.78,3837.46 h60
  text "-" at 4233.78,3832.46 h60
  text "-" at 6748.78,3782.46 h60
  text "-" at 7008.78,3777.46 h60
  text "电源开关" at 1164.78,3255 h60 r90
  text "摄像头接口" at 3814.56,2920.06 h60 r90
  text "+" at 1095,2520 h60
  text "电源接口" at 1134.95,2300 h60 r90
  text "编码器接口2" at 3889.16,2236.71 h60
  text "编码器接口3" at 4294.16,2231.71 h60
  text "-" at 1144.99,2220 h60 r90
  text "定位模块" at 4515,2185.44 h60
  text "-" at 4748.78,1987.46 h60
  text "TOF模块" at 5200,1970.44 h60
  text "-" at 3828.78,1967.46 h60
  text "-" at 4233.78,1967.46 h60
  text "-" at 5108.78,1962.46 h60
  text "有刷电机接口2" at 2685,1935 h60
  text "无刷电机接口2" at 3242.65,1933.6 h60
  text "-" at 6238.78,1862.46 h60
  text "-" at 4748.78,1857.46 h60
  text "磁铁感应模块" at 4510.06,1825.44 h60
  text "+" at 1801.52,1811.73 h60
  text "-" at 1465,1810.01 h60
  text "无线SPI" at 6260,1810.22 h60
Top Solder:
  drawing of 774 lines, arcs and shapes, not listed
Bottom Solder:
  drawing of 21 lines, arcs and shapes, not listed
Mechanical 1:
  lines w10: 1000,2062.29 ccw(c1367.29,2062.29) 1367.29,1695 ; 1000,2062.39 995.15,4100.04 cw(c1367.5,4102.54) 1364.99,4474.88 6802.71,4475 cw(c6802.71,4097.71) 7180,4097.71 7180,2067.32 cw(c6807.68,2067.32) 6807.68,1695 ; 1370,1695 6810,1695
